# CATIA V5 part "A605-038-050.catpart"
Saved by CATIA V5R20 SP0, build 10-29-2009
Part number: A605-038-050
Source: Unknown
Property "A": "0.000"
Property "ARTICLENO": "A605-038-050"
Property "BOMINFO": "A605-038-050"
Property "CODE": "A605-038-050"
Property "D": "9.000"
Property "FORM": "A"
Property "L": "50.000"
Property "L1": "20.000"
Property "LINA": "A605-038-050"
Property "NB": "A605-038-050"
Property "NBSYN": "$CODE."
Property "NN": "A605"
Property "NT": "Wear Plates, self-lubricating"
Property "SCREW": "2*M8X16"
Property "SUPPLIER": "CF"
Property "W": "38.000"
Bounding box of the stored display mesh (mm): x -38 to 0, y 0 to 5, z -50 to 0
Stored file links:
  C:\Users\Utente\Desktop\3D files A605\A605-038-050.catpart
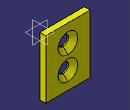
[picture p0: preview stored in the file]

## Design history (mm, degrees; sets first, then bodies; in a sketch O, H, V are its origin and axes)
Body1 "Geometry.1" (main body)
  Solid1 "A605-038-050.catpart": solid without history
